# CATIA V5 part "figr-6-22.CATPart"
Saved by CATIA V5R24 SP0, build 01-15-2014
Part number: Part1
Bounding box of the stored display mesh (mm): x 0 to 150, y -70 to 70, z -150 to 69.804
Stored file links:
  D:\KAVITA\CATIA V5-6R2014 Project_ Kavita\CATIA V5-6R2014_partfiles\Partfiles\c06_catia_v5-6r2014_prt\figr-6-22.CATPart
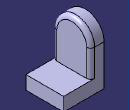
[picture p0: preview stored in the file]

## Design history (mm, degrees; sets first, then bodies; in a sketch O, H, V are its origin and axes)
Body1 (main body)
  Sketch1 on yz-plane, origin (0, 0, 0), H (0, 1, 0), V (0, 0, 1)
    arc A1 centre (0, 0) radius 70 from (70, 0) to (-70, 0) ccw
    point P1 (70, 0)
    point P2 (-70, 0)
    line L1 (-70, 0) -> (-70, -150)
    line L2 (-70, -150) -> (70, -150)
    line L3 (70, -150) -> (70, 0)
    construction circle A2 centre (0, 0) radius 37.5
    radius A1 = 70
    radius A2 = 37.5
    distance O L2 = 150
    coincidence: P1 H, P2 H
    tangency: L1 A1, L3 A1
    horizontal: L2 H
  Pad1: profile Sketch1, direction (1, 0, 0), length 50
  Sketch2 on face of Pad1, origin (50, 0, 0), H (0, 1, 0), V (0, 0, 1)
    line L1 (-70, -150) -> (70, -150)
    line L2 (70, -150) -> (70, -100)
    line L3 (70, -100) -> (-70, -100)
    line L4 (-70, -100) -> (-70, -150)
    reference projected line E1 (-70, -150) -> (70, -150) from edge [face of Pad1 | face of Pad1]
    reference projected line E2 (-70, 0) -> (-70, -150) from edge [face of Pad1 | face of Pad1]
    reference projected line E3 (70, -150) -> (70, 0) from edge [face of Pad1 | face of Pad1]
    length L2 = 50
    horizontal: L1 H, L3 H
    vertical: L2 V, L4 V
    coincidence: L1 E1, E2 L4, L2 E3
  Pad2: profile Sketch2, direction (1, 0, 0), length 100
  Fillet1: radius 15, on edge [face of Pad2 | end face of Pad1]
